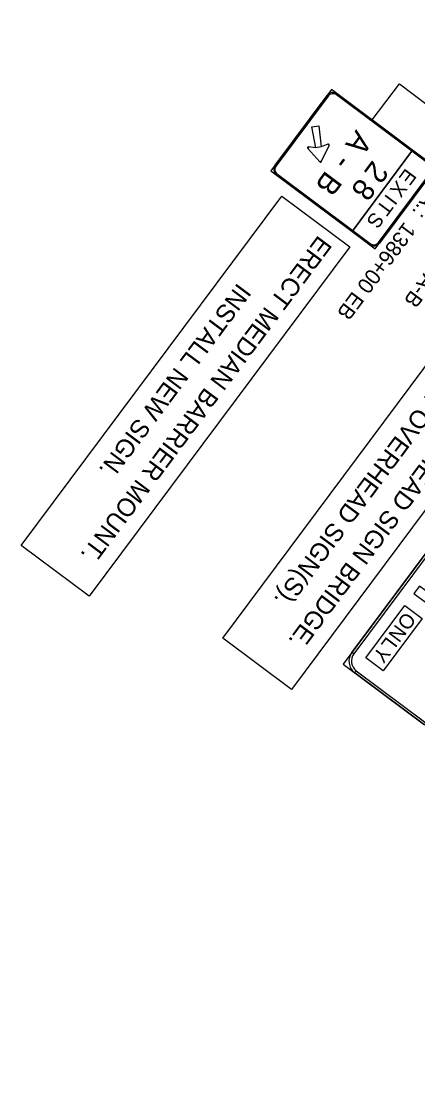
# Model space of a CAD drawing. Extents: x 2338610 to 2351914, y 366540 to 376484.
# Drawn here: x 2344914 to 2345170, y 369795 to 370482 of the extents above; entities that cross this region are included whole.
import ezdxf

# ---------------------------------------------------------------- set-up
doc = ezdxf.new("R2010")
doc.units = 0
for name, color, linetype in [('RD_PD_Final_LnLine', 7, 'Continuous'), ('RD_PD_Final_TrvlWay', 7, 'Continuous'), ('TR PM UNASSIGNED 3', 7, 'Continuous'), ('TR SN EXISTING - BREAK-AWAY SIGN SUPPORTS', 7, 'Continuous'), ('TR SN EXTRUDED PANEL SIGNS - GROUND MOUNTED', 7, 'Continuous'), ('TR SN EXTRUDED PANEL SIGNS- MOUNTED OVERHEAD', 7, 'Continuous')]:
    doc.layers.add(name, color=color, linetype=linetype)

msp = doc.modelspace()

# ---------------------------------------------------------------- linework, layer by layer
at = {"layer": 'RD_PD_Final_LnLine'}
msp.add_arc((2351872.76, 379241.01), 11000, 231.263715, 239.178507, dxfattribs=at)
msp.add_arc((2351872.76, 379241.01), 11000, 231.263715, 239.178507, dxfattribs=at)
msp.add_arc((2351872.76, 379241.01), 11000, 231.263715, 239.178507, dxfattribs=at)
msp.add_arc((2351872.76, 379241.01), 11000, 231.263715, 239.178507, dxfattribs=at)
at = {"layer": 'RD_PD_Final_TrvlWay'}
msp.add_arc((2352034, 379865.62), 11416.7, 232.99132, 241.724919, dxfattribs=at)
at = {"layer": 'TR SN EXISTING - BREAK-AWAY SIGN SUPPORTS'}
msp.add_lwpolyline([(2345126.41, 370335.59), (2344957.62, 370109.43), (2344913.61, 370142.28), (2345082.4, 370368.43)], close=True, dxfattribs=at)
at = {"layer": 'TR SN EXTRUDED PANEL SIGNS - GROUND MOUNTED'}
for p, q in [((2345140.85, 370417.7), (2345158.65, 370441.14)), ((2345158.65, 370441.14), (2345255.33, 370367.68)), ((2345111.75, 370433.57), (2345112.37, 370433.11)), ((2345117.84, 370433.9), (2345118.31, 370434.53)), ((2345112.32, 370402.07), (2345112.55, 370401.53)), ((2345112.55, 370401.53), (2345113.07, 370401.28)), ((2345099.16, 370399.25), (2345099.6, 370399.65)), ((2345099.6, 370399.65), (2345099.65, 370400.23)), ((2345078.73, 370388.03), (2345078.1, 370388.49)), ((2345107.47, 370390.92), (2345107.04, 370390.53)), ((2345108, 370390.67), (2345107.47, 370390.92)), ((2345079.05, 370381.93), (2345079.52, 370382.56)), ((2345139.63, 370337.7), (2345139.16, 370337.07)), ((2345145.72, 370338.03), (2345145.09, 370338.49))]:
    msp.add_line(p, q, dxfattribs=at)
for points in [[(2345114.55, 370437.33), (2345075.3, 370384.74), (2345127.89, 370345.48), (2345167.14, 370398.08), (2345114.55, 370437.33), (2345114.55, 370437.33)], [(2345112.37, 370433.11), (2345078.73, 370388.03), (2345078.1, 370388.49), (2345111.75, 370433.57), (2345112.37, 370433.11), (2345112.37, 370433.11)], [(2345166.67, 370397.45), (2345117.84, 370433.9), (2345118.31, 370434.53), (2345167.14, 370398.08), (2345166.67, 370397.45), (2345166.67, 370397.45)], [(2345101.89, 370413.2), (2345106.49, 370413.87), (2345107.89, 370400.26), (2345104.41, 370399.75), (2345101.89, 370413.2), (2345101.89, 370413.2)], [(2345107.47, 370390.92), (2345108, 370390.67), (2345113.07, 370401.28), (2345112.55, 370401.53), (2345112.32, 370402.07), (2345107.89, 370400.26), (2345104.41, 370399.75), (2345099.65, 370400.23), (2345099.6, 370399.65), (2345099.16, 370399.25), (2345107.04, 370390.53), (2345107.47, 370390.92), (2345107.47, 370390.92)], [(2345167.14, 370398.08), (2345127.89, 370345.48), (2345142.92, 370334.27), (2345182.17, 370386.86), (2345167.14, 370398.08), (2345167.14, 370398.08)], [(2345177.94, 370389.04), (2345166.67, 370397.45), (2345167.14, 370398.08), (2345178.41, 370389.67), (2345177.94, 370389.04), (2345177.94, 370389.04)], [(2345079.52, 370382.56), (2345128.36, 370346.11), (2345127.89, 370345.48), (2345079.05, 370381.93), (2345079.52, 370382.56), (2345079.52, 370382.56)], [(2345145.09, 370338.49), (2345178.74, 370383.57), (2345179.36, 370383.11), (2345145.72, 370338.03), (2345145.09, 370338.49), (2345145.09, 370338.49)], [(2345128.36, 370346.11), (2345139.63, 370337.7), (2345139.16, 370337.07), (2345127.89, 370345.48), (2345128.36, 370346.11), (2345128.36, 370346.11)]]:
    msp.add_lwpolyline(points, close=True, dxfattribs=at)
for centre, radius, start, end in [((2345115.5, 370430.77), 4.69, 53.26356, 143.26377), ((2345115.5, 370430.77), 3.91, 53.26356, 143.26377), ((2345112.55, 370401.53), 0.586, 334.44176, 112.22608), ((2345099.6, 370399.65), 0.586, 84.30183, 222.08558), ((2345081.86, 370385.69), 4.69, 143.26377, 233.26398), ((2345081.86, 370385.69), 3.91, 143.26377, 233.26398), ((2345107.47, 370390.92), 0.586, 222.08558, 334.44146), ((2345141.96, 370340.83), 4.69, 233.26372, 323.26393), ((2345141.96, 370340.83), 3.91, 233.26372, 323.26393)]:
    msp.add_arc(centre, radius, start, end, dxfattribs=at)
at = {"layer": 'TR SN EXTRUDED PANEL SIGNS- MOUNTED OVERHEAD'}
for p, q in [((2345318.41, 370328.53), (2345122.15, 370065.57)), ((2345136.84, 370069.59), (2345162.08, 370103.4)), ((2345162.08, 370103.4), (2345173.35, 370094.99)), ((2345173.35, 370094.99), (2345148.11, 370061.18)), ((2345129.01, 370072.15), (2345127.75, 370073.08)), ((2345122.15, 370065.57), (2345174.74, 370026.32)), ((2345148.11, 370061.18), (2345136.84, 370069.59)), ((2345129.66, 370059.96), (2345130.59, 370061.22))]:
    msp.add_line(p, q, dxfattribs=at)
for points in [[(2345288.5, 370316.77), (2345088.72, 370049.09), (2345044.11, 370082.38), (2345243.9, 370350.06)], [(2345314.05, 370320.08), (2345129.01, 370072.15), (2345127.75, 370073.08), (2345312.8, 370321.02), (2345314.05, 370320.08), (2345314.05, 370320.08)], [(2345130.59, 370061.22), (2345175.67, 370027.57), (2345174.74, 370026.32), (2345129.66, 370059.96), (2345130.59, 370061.22), (2345130.59, 370061.22)]]:
    msp.add_lwpolyline(points, close=True, dxfattribs=at)
msp.add_lwpolyline([(2345179.79, 370109.84), (2345171.54, 370116.08), (2345167.91, 370111.22), (2345176.31, 370104.95)], dxfattribs=at)
for radius in [9.38, 7.81]:
    msp.add_arc((2345135.27, 370067.48), radius, 143.26377, 233.26398, dxfattribs=at)

# ---------------------------------------------------------------- texts
at = {"layer": 'TR PM UNASSIGNED 3'}
for s, p in [('STA.:  1386+00 EB', (2345186.36, 370385.06)), ('E5-1A-28 A-B', (2345210.4, 370367.11))]:
    msp.add_text(s, height=10, rotation=233.26372, dxfattribs=at).set_placement(p)
at = {"layer": 'TR SN EXISTING - BREAK-AWAY SIGN SUPPORTS'}
for s, p in [('ERECT MEDIAN BARRIER MOUNT.', (2345106.19, 370343.61)), ('INSTALL NEW SIGN.', (2345053.95, 370312.79))]:
    msp.add_text(s, height=11.7187, rotation=233.2638, dxfattribs=at).set_placement(p)
at = {"layer": 'TR SN EXTRUDED PANEL SIGNS - GROUND MOUNTED'}
for s, height, p in [('A', 14.06, (2345130.64, 370411.84)), ('-', 14.06, (2345118.96, 370396.19)), ('2', 14.06, (2345141.32, 370392.19)), ('B', 14.06, (2345111.01, 370385.54)), ('E', 9.38, (2345162.73, 370386.94)), ('8', 14.06, (2345132.89, 370380.89)), ('X', 9.38, (2345156.88, 370379.1)), ('I', 9.38, (2345150.33, 370370.32)), ('T', 9.38, (2345147.63, 370366.71)), ('S', 9.38, (2345141.78, 370358.87))]:
    msp.add_text(s, height=height, rotation=233.26372, dxfattribs=at).set_placement(p)
at = {"layer": 'TR SN EXTRUDED PANEL SIGNS- MOUNTED OVERHEAD'}
for s, height, rotation, p in [('INSTALL NEW OVERHEAD SIGN(S).', 11.7187, 233.2638, (2345235.11, 370319.54)), ('ERECT NEW OVERHEAD SIGN BRIDGE.', 11.7187, 233.2638, (2345264.24, 370319.38)), ('O', 9.38, 233.26372, (2345162.4, 370099.91)), ('N', 9.38, 233.26372, (2345156.31, 370091.75)), ('L', 9.38, 233.26372, (2345150.39, 370083.83)), ('Y', 9.38, 233.26372, (2345145.89, 370077.79))]:
    msp.add_text(s, height=height, rotation=rotation, dxfattribs=at).set_placement(p)

doc.saveas('drawing.dxf')
